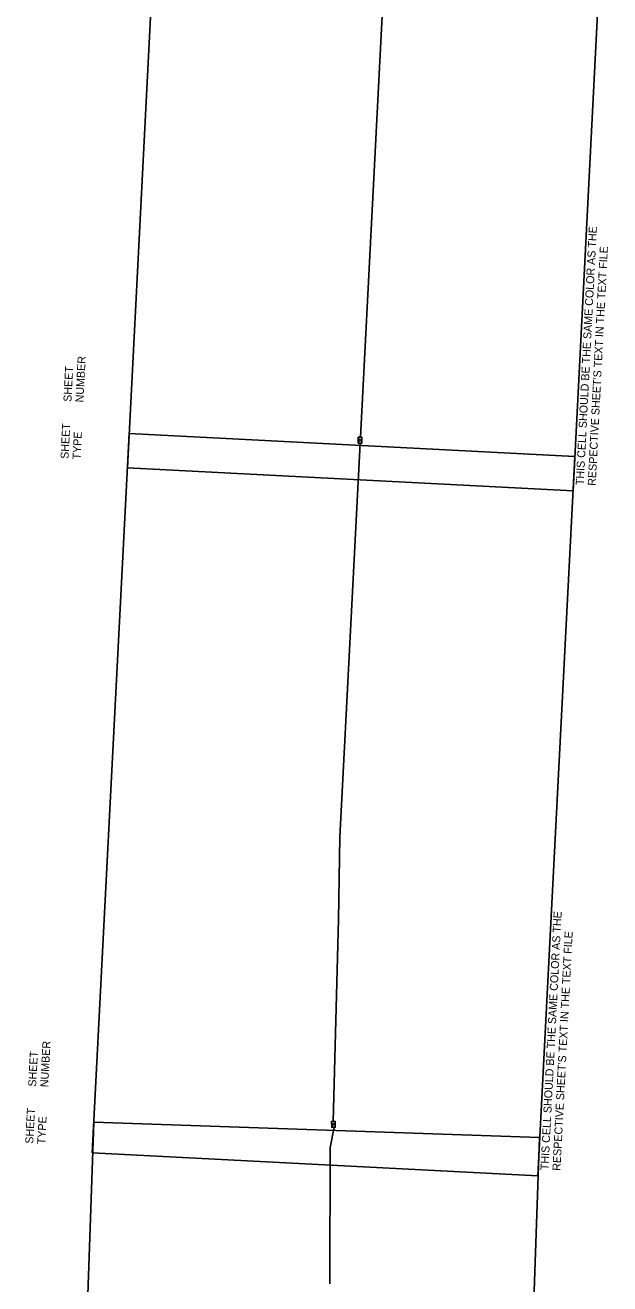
# Model space of a CAD drawing. Extents: x 601462 to 605493, y 331960 to 402715.
# Drawn here: x 602297 to 603574, y 388855 to 391608 of the extents above; entities that cross this region are included whole.
import ezdxf

# ---------------------------------------------------------------- set-up
doc = ezdxf.new("R2010")
doc.units = 0
for name, color, linetype in [('P_FTMS', 7, 'Continuous'), ('P_FTMSConduit', 7, 'Continuous'), ('P_MISC_TXT_1A (Construction)', 7, 'Continuous'), ('P_MISC_TXT_1B (Construction)', 7, 'Continuous')]:
    doc.layers.add(name, color=color, linetype=linetype)

# ---------------------------------------------------------------- blocks, each defined once
blk = doc.blocks.new('FTMS_FCV')
at = {"layer": 'P_FTMS'}
blk.add_line((13, 16), (1, -22), dxfattribs=at)
blk.add_lwpolyline([(39, 24), (-39, 24), (-39, -24), (39, -24)], close=True, dxfattribs=at)
blk.add_lwpolyline([(-12, 16), (1, -22)], dxfattribs=at)

msp = doc.modelspace()

# ---------------------------------------------------------------- linework, layer by layer
at = {"layer": 'P_FTMSConduit'}
for p, q in [((602969.9, 389210.6), (602981.2, 389652.1)), ((602963.4, 389153.6), (602971.7, 389197.8)), ((602962.5, 388855.3), (602963.5, 389154))]:
    msp.add_line(p, q, dxfattribs=at)
for points in [[(603029.4, 390707), (603101.5, 392111.6)], [(602981.2, 389652.4), (602984.4, 389832.2), (603028.7, 390694.2)]]:
    msp.add_lwpolyline(points, dxfattribs=at)
at = {"layer": 'P_MISC_TXT_1A (Construction)'}
for points in [[(603494.1, 390590), (603574.4, 392162.9), (602600.6, 392212.6), (602520.3, 390639.7)], [(603494.1, 390590), (603574.4, 392162.9), (602600.6, 392212.6), (602520.3, 390639.7)], [(603366.3, 387601.4), (603420.8, 389175.4), (602446.4, 389209.1), (602391.9, 387635.1)], [(603366.3, 387601.4), (603420.8, 389175.4), (602446.4, 389209.1), (602391.9, 387635.1)]]:
    msp.add_lwpolyline(points, close=True, dxfattribs=at)
at = {"layer": 'P_MISC_TXT_1B (Construction)'}
msp.add_lwpolyline([(603417, 389091.8), (603497.9, 390664.7), (602524.2, 390714.8), (602443.3, 389141.9)], close=True, dxfattribs=at)
msp.add_lwpolyline([(603417, 389091.8), (603497.9, 390664.7), (602524.2, 390714.8), (602443.3, 389141.9)], close=True, dxfattribs=at)

# ---------------------------------------------------------------- block references
at = {"layer": 'P_FTMS', "xscale": 0.16404166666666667, "yscale": 0.1640416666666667, "rotation": 90.75145918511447}
for p in [(603028.5, 390700.6), (602970.5, 389204.2)]:
    msp.add_blockref('FTMS_FCV', p, dxfattribs=at)

# ---------------------------------------------------------------- texts
at = {"layer": 'P_MISC_TXT_1A (Construction)'}
for s, p in [('THIS CELL SHOULD BE THE SAME COLOR AS THE', (603517.3, 390601.8)), ('THIS CELL SHOULD BE THE SAME COLOR AS THE', (603517.3, 390601.8)), ("RESPECTIVE SHEET'S TEXT IN THE TEXT FILE", (603543.5, 390600.4)), ("RESPECTIVE SHEET'S TEXT IN THE TEXT FILE", (603543.5, 390600.4)), ('NUMBER', (602423.9, 390782.8)), ('NUMBER', (602423.9, 390782.8)), ('SHEET', (602397.7, 390784.1)), ('SHEET', (602397.7, 390784.1)), ('SHEET', (602391.3, 390659.3)), ('SHEET', (602391.3, 390659.3)), ('TYPE', (602417.5, 390657.9)), ('TYPE', (602417.5, 390657.9))]:
    msp.add_text(s, height=17.5, rotation=87.0776, dxfattribs=at).set_placement(p)
at = {"layer": 'P_MISC_TXT_1B (Construction)'}
for s, p in [('THIS CELL SHOULD BE THE SAME COLOR AS THE', (603440.2, 389103.6)), ('THIS CELL SHOULD BE THE SAME COLOR AS THE', (603440.2, 389103.6)), ("RESPECTIVE SHEET'S TEXT IN THE TEXT FILE", (603466.4, 389102.2)), ("RESPECTIVE SHEET'S TEXT IN THE TEXT FILE", (603466.4, 389102.2)), ('NUMBER', (602346.9, 389285)), ('NUMBER', (602346.9, 389285)), ('SHEET', (602320.6, 389286.3)), ('SHEET', (602320.6, 389286.3)), ('SHEET', (602314.2, 389161.5)), ('SHEET', (602314.2, 389161.5)), ('TYPE', (602340.4, 389160.1)), ('TYPE', (602340.4, 389160.1))]:
    msp.add_text(s, height=17.5, rotation=87.0548, dxfattribs=at).set_placement(p)

doc.saveas('drawing.dxf')
